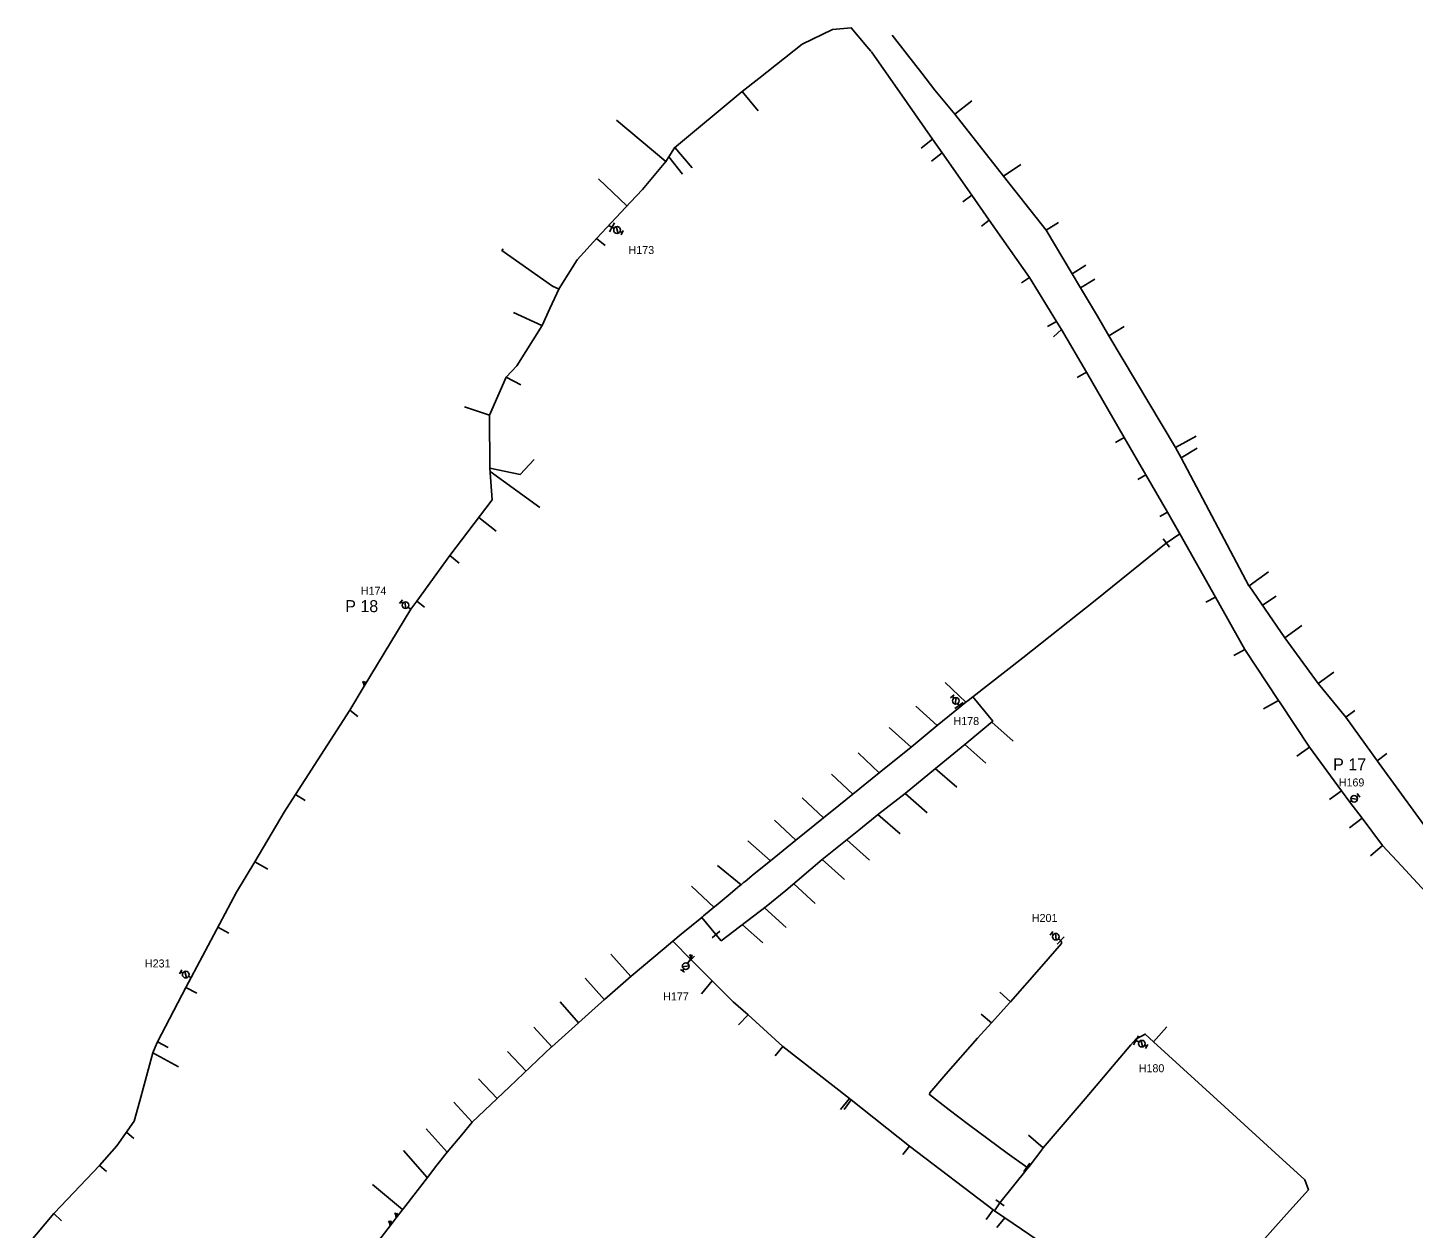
# Model space of a CAD drawing. Extents: x -548873 to -538270, y -1201997 to -1192514.
# Drawn here: x -544810.3 to -544463.9, y -1192955.8 to -1192655.7 of the extents above; entities that cross this region are included whole.
import ezdxf

# ---------------------------------------------------------------- set-up
doc = ezdxf.new("R2010")
doc.units = 0
for name, color, linetype in [('KN_HRAN_STÁTNÍ', 7, 'Continuous'), ('KN_PARC_Č', 7, 'Continuous'), ('KN_VKP_HRAN_SPORNÁ', 7, 'Continuous'), ('PK_PARC_Čv', 7, 'Continuous'), ('Vrstva 29', 7, 'Continuous'), ('Vrstva 39', 7, 'Continuous')]:
    doc.layers.add(name, color=color, linetype=linetype)

# ---------------------------------------------------------------- blocks, each defined once
blk = doc.blocks.new('160')
at = {"layer": 'KN_HRAN_STÁTNÍ'}
blk.add_circle((0, 0), 0.0458, dxfattribs=at)
blk = doc.blocks.new('147')
at = {"layer": 'KN_HRAN_STÁTNÍ'}
blk.add_line((0, 1.27), (0, -1.27), dxfattribs=at)
blk = doc.blocks.new('133')
at = {"layer": 'KN_HRAN_STÁTNÍ'}
for p, q in [((0.28, 0), (0, 0)), ((0.54, 0.58), (1.7, -0.58)), ((1.94, 0), (2.52, 0)), ((2.52, 0.58), (2.52, -0.58))]:
    blk.add_line(p, q, dxfattribs=at)
blk.add_circle((1.11, 0), 0.825, dxfattribs=at)
blk = doc.blocks.new('150')
at = {"layer": 'KN_HRAN_STÁTNÍ'}
blk.add_line((0, 1.27), (0, -1.27), dxfattribs=at)
blk = doc.blocks.new('128')
at = {"layer": 'KN_HRAN_STÁTNÍ'}
for p, q in [((-0.19, 1.06), (-0.43, 1.15)), ((-0.36, 0.84), (-0.19, 1.06)), ((-0.19, 1.06), (-0.02, 1.25)), ((-0.19, 1.06), (0, 0)), ((0.05, 0.95), (-0.19, 1.06)), ((-0.1, 1), (0.41, 0.91)), ((-0.07, 0.82), (0.17, 0.96)), ((0.17, 0.96), (-0.02, 1.13)), ((0.17, 0.96), (0, 0)), ((0.19, 1.21), (0.17, 0.96)), ((0.17, 0.96), (0.38, 1.08)), ((0.36, 0.77), (0.17, 0.96))]:
    blk.add_line(p, q, dxfattribs=at)

msp = doc.modelspace()

# ---------------------------------------------------------------- linework, layer by layer
at = {"layer": 'KN_PARC_Č'}
for points in [[(-544631.666, -1192671.644), (-544627.649, -1192676.512)], [(-544578.502, -1192677.353), (-544574.232, -1192673.974)], [(-544650.732, -1192689.166), (-544663.1, -1192678.817)], [(-544584.083, -1192683.553), (-544586.959, -1192685.847)], [(-544648.543, -1192685.648), (-544644.211, -1192690.746)], [(-544581.707, -1192686.947), (-544584.378, -1192689.08)], [(-544650.047, -1192687.96), (-544646.589, -1192692.339)], [(-544566.326, -1192692.843), (-544562.003, -1192689.898)], [(-544660.476, -1192700.253), (-544667.577, -1192693.493)], [(-544574.3, -1192697.531), (-544576.484, -1192699.202)], [(-544569.899, -1192703.82), (-544571.824, -1192705.293)], [(-544555.667, -1192706.307), (-544552.603, -1192704.381)], [(-544677.462, -1192721.073), (-544679.06, -1192720.336), (-544691.741, -1192711.386), (-544691.444, -1192710.944)], [(-544668.117, -1192708.368), (-544665.96, -1192710.17)], [(-544549.166, -1192717.265), (-544545.744, -1192715.065)], [(-544559.813, -1192718.11), (-544561.859, -1192719.496)], [(-544547.083, -1192720.762), (-544543.532, -1192718.557)], [(-544681.732, -1192730.173), (-544688.848, -1192726.918)], [(-544553.095, -1192729.106), (-544555.341, -1192730.399)], [(-544551.834, -1192731.169), (-544553.86, -1192732.97)], [(-544539.978, -1192732.689), (-544536.217, -1192730.379)], [(-544545.594, -1192741.804), (-544547.95, -1192743.18)], [(-544690.713, -1192743.093), (-544687.022, -1192744.997)], [(-544694.863, -1192752.579), (-544701.07, -1192750.51)], [(-544536.158, -1192758.1), (-544538.314, -1192759.402)], [(-544523.35, -1192760.603), (-544518.21, -1192757.81)], [(-544694.765, -1192765.82), (-544687.17, -1192767.37), (-544683.688, -1192763.625)], [(-544521.96, -1192763.217), (-544517.96, -1192760.832)], [(-544694.704, -1192766.607), (-544682.288, -1192775.61)], [(-544530.742, -1192767.49), (-544532.731, -1192768.673)], [(-544525.387, -1192776.776), (-544527.25, -1192777.884)], [(-544697.496, -1192778.107), (-544693.21, -1192781.554)], [(-544704.796, -1192787.625), (-544702.392, -1192789.526)], [(-544504.975, -1192795.19), (-544500.117, -1192791.742)], [(-544513.376, -1192798.037), (-544515.798, -1192799.311)], [(-544501.606, -1192800.075), (-544498.205, -1192797.82)], [(-544713.035, -1192799.034), (-544711.13, -1192800.554)], [(-544496.017, -1192808.179), (-544491.761, -1192805.104)], [(-544506.036, -1192811.124), (-544508.791, -1192812.624)], [(-544487.685, -1192819.633), (-544483.727, -1192816.823)], [(-544575.734, -1192824.292), (-544580.951, -1192819.379)], [(-544582.903, -1192830.128), (-544588.303, -1192825.314)], [(-544497.561, -1192823.899), (-544501.347, -1192825.989)], [(-544729.796, -1192826.252), (-544727.732, -1192827.836)], [(-544569.258, -1192829.257), (-544563.896, -1192833.994)], [(-544480.799, -1192828.039), (-544478.553, -1192826.4)], [(-544589.453, -1192835.506), (-544594.969, -1192830.589)], [(-544576.033, -1192834.832), (-544570.743, -1192839.557)], [(-544489.85, -1192835.523), (-544493.055, -1192837.814)], [(-544597.391, -1192841.939), (-544602.675, -1192836.97)], [(-544472.898, -1192838.937), (-544470.527, -1192837.128)], [(-544604, -1192847.281), (-544609.329, -1192842.253)], [(-544583.403, -1192840.897), (-544577.996, -1192845.571)], [(-544481.812, -1192846.442), (-544484.832, -1192848.643)], [(-544743.342, -1192847.335), (-544740.897, -1192848.859)], [(-544611.327, -1192853.204), (-544616.711, -1192848.158)], [(-544590.937, -1192847.096), (-544585.447, -1192851.92)], [(-544618.257, -1192858.806), (-544623.628, -1192853.742)], [(-544597.742, -1192852.391), (-544592.203, -1192857.235)], [(-544476.718, -1192853.284), (-544479.826, -1192855.722)], [(-544624.621, -1192863.951), (-544630.291, -1192858.921)], [(-544605.533, -1192858.726), (-544599.868, -1192863.794)], [(-544471.604, -1192860.1), (-544474.617, -1192862.655)], [(-544611.666, -1192863.618), (-544606.111, -1192868.598)], [(-544753.483, -1192864.232), (-544750.29, -1192866.065)], [(-544631.962, -1192869.903), (-544637.86, -1192865.1)], [(-544638.73, -1192875.524), (-544644.37, -1192870.284)], [(-544618.8, -1192869.674), (-544613.397, -1192874.604)], [(-544626.057, -1192875.675), (-544620.7, -1192880.627)], [(-544762.741, -1192880.564), (-544759.98, -1192882.027)], [(-544631.599, -1192879.913), (-544626.521, -1192884.438)], [(-544659.55, -1192892.821), (-544664.506, -1192887.24)], [(-544666.087, -1192898.651), (-544670.901, -1192893.277)], [(-544639.155, -1192893.968), (-544641.819, -1192897.201)], [(-544770.74, -1192895.578), (-544768.027, -1192897.061)], [(-544564.578, -1192899.147), (-544567.257, -1192896.795)], [(-544672.612, -1192904.469), (-544677.153, -1192899.195)], [(-544679.271, -1192910.406), (-544683.798, -1192905.489)], [(-544630.212, -1192902.461), (-544632.61, -1192904.947)], [(-544569.34, -1192904.428), (-544571.907, -1192902.236)], [(-544528.832, -1192909.155), (-544525.507, -1192905.476)], [(-544777.801, -1192909.156), (-544775.18, -1192910.585)], [(-544778.979, -1192911.92), (-544772.559, -1192915.425)], [(-544685.703, -1192916.507), (-544690.345, -1192911.616)], [(-544621.478, -1192910.315), (-544623.407, -1192912.654)], [(-544692.905, -1192923.349), (-544697.614, -1192918.414)], [(-544699.139, -1192929.281), (-544703.725, -1192924.297)], [(-544604.855, -1192923.379), (-544607.072, -1192926.127)], [(-544604.444, -1192923.702), (-544606.179, -1192926.095)], [(-544785.619, -1192931.787), (-544783.756, -1192933.316)], [(-544705.42, -1192936.783), (-544710.709, -1192930.891)], [(-544556.432, -1192935.697), (-544560.082, -1192932.492)], [(-544710.384, -1192943.103), (-544716.339, -1192936.368)], [(-544589.832, -1192935.238), (-544591.542, -1192937.382)], [(-544792.376, -1192940.084), (-544790.563, -1192941.583)], [(-544716.571, -1192951.114), (-544724.098, -1192944.876)], [(-544803.761, -1192952.099), (-544801.831, -1192953.918)], [(-544568.911, -1192951.187), (-544570.697, -1192953.552)], [(-544566.053, -1192953.153), (-544568.05, -1192955.626)]]:
    msp.add_lwpolyline(points, dxfattribs=at)
at = {"layer": 'KN_VKP_HRAN_SPORNÁ'}
for points in [[(-544599.51, -1192661.539), (-544600.479, -1192660.391), (-544604.426, -1192655.713), (-544609.108, -1192656.166), (-544616.671, -1192659.848), (-544627.505, -1192668.369), (-544631.644, -1192671.625), (-544648.61, -1192685.704), (-544650.047, -1192687.96), (-544650.732, -1192689.166)], [(-544459.036, -1192858.059), (-544472.431, -1192839.582), (-544480.799, -1192828.039), (-544487.685, -1192819.633), (-544496.017, -1192808.179), (-544504.975, -1192795.19), (-544504.982, -1192795.18), (-544521.958, -1192763.219), (-544521.961, -1192763.214), (-544523.35, -1192760.604), (-544539.978, -1192732.69), (-544542.874, -1192727.828), (-544547.081, -1192720.764), (-544549.166, -1192717.265), (-544555.645, -1192706.335), (-544566.326, -1192692.843), (-544578.501, -1192677.354), (-544583.532, -1192671.318), (-544586.785, -1192667.11), (-544590.345, -1192662.504), (-544594.156, -1192657.575)], [(-544599.382, -1192661.691), (-544599.363, -1192661.718), (-544590.433, -1192674.478), (-544584.083, -1192683.553), (-544581.707, -1192686.947), (-544574.3, -1192697.531), (-544569.899, -1192703.82), (-544559.813, -1192718.11), (-544557.572, -1192721.778), (-544553.095, -1192729.106), (-544551.834, -1192731.169), (-544545.594, -1192741.804), (-544536.159, -1192758.098), (-544536.157, -1192758.102), (-544530.742, -1192767.49), (-544525.387, -1192776.776), (-544523.956, -1192779.257), (-544522.274, -1192782.174)], [(-544650.732, -1192689.166), (-544656.602, -1192696.14), (-544659.571, -1192699.291), (-544668.036, -1192708.278), (-544672.939, -1192713.712), (-544677.391, -1192720.921), (-544679.726, -1192725.907), (-544681.698, -1192730.119), (-544687.989, -1192740.249), (-544690.689, -1192743.039), (-544694.863, -1192752.579)], [(-544694.863, -1192752.579), (-544694.765, -1192765.82), (-544694.151, -1192773.746), (-544704.798, -1192787.628), (-544713.035, -1192799.034), (-544714.544, -1192801.079), (-544726.194, -1192820.307)], [(-544525.649, -1192784.509), (-544522.274, -1192782.174)], [(-544522.274, -1192782.174), (-544513.376, -1192798.037), (-544506.036, -1192811.124), (-544497.561, -1192823.899), (-544497.216, -1192824.419), (-544489.85, -1192835.523), (-544481.812, -1192846.442), (-544479.742, -1192849.254), (-544476.718, -1192853.284), (-544471.592, -1192860.113), (-544466.868, -1192865.198), (-544456.739, -1192876.102)], [(-544574.016, -1192822.939), (-544561.517, -1192813.178), (-544543.455, -1192798.908), (-544525.649, -1192784.509)], [(-544726.194, -1192820.307), (-544729.796, -1192826.252), (-544743.342, -1192847.335), (-544746.212, -1192851.802), (-544753.483, -1192864.232), (-544758.07, -1192871.796), (-544769.433, -1192893.125), (-544770.74, -1192895.578), (-544770.744, -1192895.585), (-544777.801, -1192909.156), (-544778.39, -1192910.538), (-544778.979, -1192911.92), (-544782.275, -1192923.969), (-544783.647, -1192928.986), (-544788.003, -1192935.173), (-544792.376, -1192940.084), (-544803.709, -1192952.037), (-544803.761, -1192952.099), (-544810.284, -1192959.825)], [(-544641.795, -1192878.07), (-544641.337, -1192877.689), (-544639.442, -1192876.115), (-544637.693, -1192874.663), (-544635.19, -1192872.584), (-544632.351, -1192870.226), (-544631.962, -1192869.903), (-544631.329, -1192869.377), (-544631.203, -1192869.273), (-544630.959, -1192869.075), (-544629.297, -1192867.732), (-544629.074, -1192867.551), (-544624.62, -1192863.951), (-544618.257, -1192858.807), (-544611.329, -1192853.206), (-544607.479, -1192850.094), (-544604.003, -1192847.283), (-544597.392, -1192841.939), (-544589.453, -1192835.506), (-544582.903, -1192830.128), (-544577.214, -1192825.458), (-544575.731, -1192824.29), (-544575.197, -1192823.869), (-544574.016, -1192822.939)], [(-544638.228, -1192882.348), (-544636.905, -1192883.935), (-544625.664, -1192875.376), (-544620.801, -1192871.373), (-544611.638, -1192863.594), (-544602.481, -1192856.292), (-544597.48, -1192852.176), (-544590.913, -1192847.077), (-544583.337, -1192840.842), (-544576.033, -1192834.832), (-544569.026, -1192829.066), (-544574.016, -1192822.939)], [(-544649.004, -1192884.061), (-544646.906, -1192882.314), (-544641.795, -1192878.07)], [(-544641.795, -1192878.07), (-544638.228, -1192882.348)], [(-544718.171, -1192953.183), (-544715.751, -1192950.054), (-544710.38, -1192943.098), (-544707.995, -1192940.009), (-544705.42, -1192936.783), (-544701.781, -1192932.434), (-544699.155, -1192929.296), (-544689.841, -1192920.434), (-544679.317, -1192910.447), (-544679.271, -1192910.406), (-544669.243, -1192901.466), (-544666.081, -1192898.645), (-544659.463, -1192892.743), (-544651.209, -1192885.888), (-544649.004, -1192884.061)], [(-544649.004, -1192884.061), (-544644.471, -1192888.636)], [(-544560.51, -1192940.55), (-544565.43, -1192936.98), (-544570.3, -1192933.42), (-544575.08, -1192929.82), (-544579.91, -1192926.14), (-544584.85, -1192922.35), (-544584.8, -1192921.91), (-544580.73, -1192917.25), (-544572.81, -1192908.27), (-544569.34, -1192904.428), (-544564.79, -1192899.39), (-544564.578, -1192899.147), (-544556.88, -1192890.34), (-544551.86, -1192884.61), (-544551.82, -1192884.31), (-544551.82, -1192884.13), (-544551.98, -1192883.937)], [(-544568.615, -1192951.413), (-544589.831, -1192935.239), (-544604.446, -1192923.7), (-544604.854, -1192923.379), (-544621.478, -1192910.315), (-544630.212, -1192902.461), (-544633.914, -1192899.224), (-544644.471, -1192888.636)], [(-544560.275, -1192940.72), (-544559.97, -1192940.35), (-544557.033, -1192936.489), (-544556.428, -1192935.692), (-544545.966, -1192923.41), (-544534.516, -1192909.967), (-544533.273, -1192908.508), (-544530.926, -1192907.242), (-544528.833, -1192909.155), (-544521.348, -1192915.993), (-544512.949, -1192923.667), (-544498.441, -1192936.942), (-544491.038, -1192943.716), (-544490.115, -1192946.195), (-544495.563, -1192952.279), (-544513.363, -1192972.156), (-544513.04, -1192974.001), (-544513.001, -1192974.228), (-544512.946, -1192974.544), (-544512.868, -1192974.987), (-544512.752, -1192975.65), (-544512.058, -1192979.621)], [(-544567.248, -1192949.461), (-544560.44, -1192940.92), (-544560.275, -1192940.72)], [(-544560.275, -1192940.72), (-544560.51, -1192940.55)], [(-544568.615, -1192951.413), (-544567.248, -1192949.461)], [(-544719.7, -1192955.161), (-544718.171, -1192953.183)], [(-544456.83, -1193077.14), (-544464.218, -1193063.134), (-544464.277, -1193063.026), (-544484.158, -1193026.242), (-544488.072, -1193019.795), (-544494.802, -1193008.711), (-544494.915, -1193008.609), (-544497.144, -1193006.604), (-544499.581, -1193004.404), (-544504.015, -1193000.08), (-544513.635, -1192990.699), (-544522.182, -1192982.943), (-544539.415, -1192971.241), (-544566.053, -1192953.153), (-544568.615, -1192951.413)], [(-544725.84, -1192963.12), (-544723.689, -1192960.321), (-544719.7, -1192955.161)]]:
    msp.add_lwpolyline(points, dxfattribs=at)
at = {"layer": 'PK_PARC_Čv'}
for points in [[(-544665.112, -1192705.174), (-544663.96, -1192705.75)], [(-544714.544, -1192801.079), (-544714.99, -1192800.73)], [(-544577.214, -1192825.458), (-544577.446, -1192825.135), (-544577.64, -1192824.865)], [(-544479.742, -1192849.254), (-544479.57, -1192849.12)], [(-544551.98, -1192883.937), (-544552.06, -1192883.84), (-544552.37, -1192883.59)], [(-544644.581, -1192888.525), (-544645.173, -1192889.379)], [(-544769.433, -1192893.125), (-544769.805, -1192892.927)], [(-544533.435, -1192908.699), (-544532.744, -1192909.097)]]:
    msp.add_lwpolyline(points, dxfattribs=at)

# ---------------------------------------------------------------- block references
for name, p, xscale, yscale, rotation in [('150', (-544664.22, -1192705.62), 1.0138865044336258, 1.0138865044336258, -27.56531359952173), ('133', (-544663.96, -1192705.75), 1.0138865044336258, 1.0138865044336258, -27.56531359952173), ('133', (-544714.99, -1192800.73), 1.000000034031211, 1.0000000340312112, 141.99999959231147), ('133', (-544577.64, -1192824.865), 1.000000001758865, 1.000000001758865, 125.99999933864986), ('150', (-544577.446, -1192825.135), 1.000000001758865, 1.000000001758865, -54.00000066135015), ('133', (-544479.57, -1192849.12), 1.000000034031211, 1.0000000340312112, 38.000000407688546), ('133', (-544552.37, -1192883.59), 1.000000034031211, 1.0000000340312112, 141.99999959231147), ('150', (-544552.06, -1192883.84), 1.0000000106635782, 1.0000000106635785, -44.00000165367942), ('133', (-544769.805, -1192892.927), 1.0072562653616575, 1.0072562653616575, 151.23333487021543), ('133', (-544645.173, -1192889.379), 0.9999999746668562, 0.999999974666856, -124.00000045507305), ('150', (-544533.215, -1192908.826), 1.0037042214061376, 1.0037042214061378, -29.379208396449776), ('133', (-544532.744, -1192909.097), 1.0037042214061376, 1.0037042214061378, -29.379208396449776)]:
    msp.add_blockref(name, p, dxfattribs=dict(at, xscale=xscale, yscale=yscale, rotation=rotation))
at = {"layer": 'Vrstva 29'}
for name, p, xscale, yscale, rotation in [('160', (-544650.732, -1192689.166), 0.9999999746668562, 0.999999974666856, 55.999999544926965), ('160', (-544694.863, -1192752.579), 0.999999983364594, 0.9999999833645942, -101.0000002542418), ('147', (-544525.649, -1192784.509), 0.9999999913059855, 0.9999999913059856, 37.00000193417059), ('160', (-544522.274, -1192782.174), 0.9999999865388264, 0.9999999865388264, -59.99999955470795), ('160', (-544726.194, -1192820.307), 1.0000000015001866, 1.0000000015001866, -120.99999982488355), ('160', (-544574.016, -1192822.939), 1.000000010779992, 1.0000000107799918, 38.9999989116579), ('160', (-544641.795, -1192878.07), 1.000000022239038, 1.0000000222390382, -94.99999998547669), ('160', (-544649.004, -1192884.061), 1.0000000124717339, 1.0000000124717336, 40.00000131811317), ('147', (-544638.228, -1192882.348), 1.0000000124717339, 1.0000000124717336, 130.0000013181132), ('160', (-544551.98, -1192883.937), 1.0000000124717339, 1.0000000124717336, -49.99999868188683), ('147', (-544644.471, -1192888.636), 0.999999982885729, 0.9999999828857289, -45), ('147', (-544560.51, -1192940.55), 1.000000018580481, 1.000000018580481, 144.99999976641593), ('160', (-544560.275, -1192940.72), 0.9999999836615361, 0.9999999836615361, -81.99999961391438), ('147', (-544567.248, -1192949.461), 1.000000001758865, 1.000000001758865, -125.99999933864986), ('160', (-544718.171, -1192953.183), 0.9999999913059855, 0.9999999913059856, 52.999998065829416), ('160', (-544568.615, -1192951.413), 1.008377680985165, 1.0083776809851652, 11.626378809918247), ('160', (-544719.7, -1192955.161), 0.9999999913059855, 0.9999999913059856, 52.999998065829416)]:
    msp.add_blockref(name, p, dxfattribs=dict(at, xscale=xscale, yscale=yscale, rotation=rotation))
at = {"layer": 'Vrstva 39'}
for p in [(-544726.194, -1192820.307), (-544644.471, -1192888.636), (-544719.7, -1192955.161), (-544718.171, -1192953.183)]:
    msp.add_blockref('128', p, dxfattribs=at)

# ---------------------------------------------------------------- texts
at = {"layer": 'PK_PARC_Čv'}
for s, height, p in [('H173', 2, (-544660.07, -1192712.27)), ('H174', 2, (-544727.01, -1192797.46)), ('P 18', 3, (-544730.91, -1192801.79)), ('H178', 2, (-544578.84, -1192830.005)), ('P 17', 3, (-544483.94, -1192841.35)), ('H169', 2, (-544482.53, -1192845.35)), ('H201', 2, (-544559.26, -1192879.22)), ('H231', 2, (-544780.985, -1192890.597)), ('H177', 2, (-544651.433, -1192898.849)), ('H180', 2, (-544532.534, -1192916.787))]:
    msp.add_text(s, height=height, dxfattribs=at).set_placement(p)

doc.saveas('drawing.dxf')
